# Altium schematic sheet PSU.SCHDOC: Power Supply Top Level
size A4; Organization: Altium Limited.; Address1: Level 3, 12a Rodborough Rd; Address2: Frenchs Forest 2086; Address3: NSW; Address4: AUSTRALIA; DocumentNumber: 10; SheetNumber: 10; SheetTotal: 23
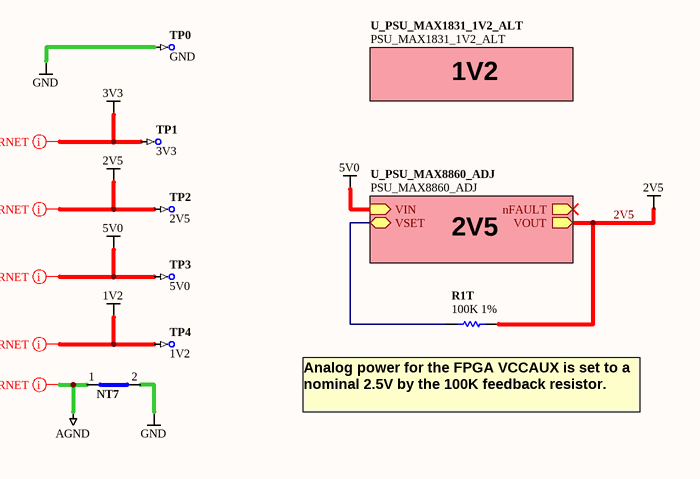
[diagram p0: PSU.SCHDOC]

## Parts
NT7  Net Tie SMT2  [NETTIE-SMT2-8X8]  (value not drawn)  (net tie, no BOM)
R1T  100K 1%  [RESC1005-STAR]
TP0  GND  [TestPin]  (no BOM)
TP1  3V3  [TestPin]  (no BOM)
TP2  2V5  [TestPin]  (no BOM)
TP3  5V0  [TestPin]  (no BOM)
TP4  1V2  [TestPin]  (no BOM)

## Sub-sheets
U_PSU_MAX1831_1V2_ALT = PSU_MAX1831_1V2_ALT: no entries
U_PSU_MAX8860_ADJ = PSU_MAX8860_ADJ: nFAULT (out), VIN (in), VOUT (out), VSET (bidir)

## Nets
1V2: TP4.1
2V5: R1T.2 TP2.1 ; sheet U_PSU_MAX8860_ADJ/VOUT
3V3: TP1.1
5V0: TP3.1 ; sheet U_PSU_MAX8860_ADJ/VIN
AGND: NT7.1(Net1)
GND: NT7.2(Net2) TP0.1
NetR1T_1: R1T.1 ; sheet U_PSU_MAX8860_ADJ/VSET

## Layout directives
net class PWRNET: 1V2, 2V5, 3V3, 5V0, AGND

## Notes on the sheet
- 1V2
- 2V5
- (near R1T) Analog power for the FPGA VCCAUX is set to a nominal 2.5V by the 100K feedback resistor.

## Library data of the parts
NT7 = D-002-0002: Net-Tie, Surface Mount, 2 x 0.4mm x 0.2mm SMT Pads - For 0.2mm Track
R1T = D-100-0132: Resistor, 100K 1% 0402 (1005); Power Rating: 63 mW
TP0-TP4 = D-006-0000: Test Point, PCB Mount with Silkscreen Box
